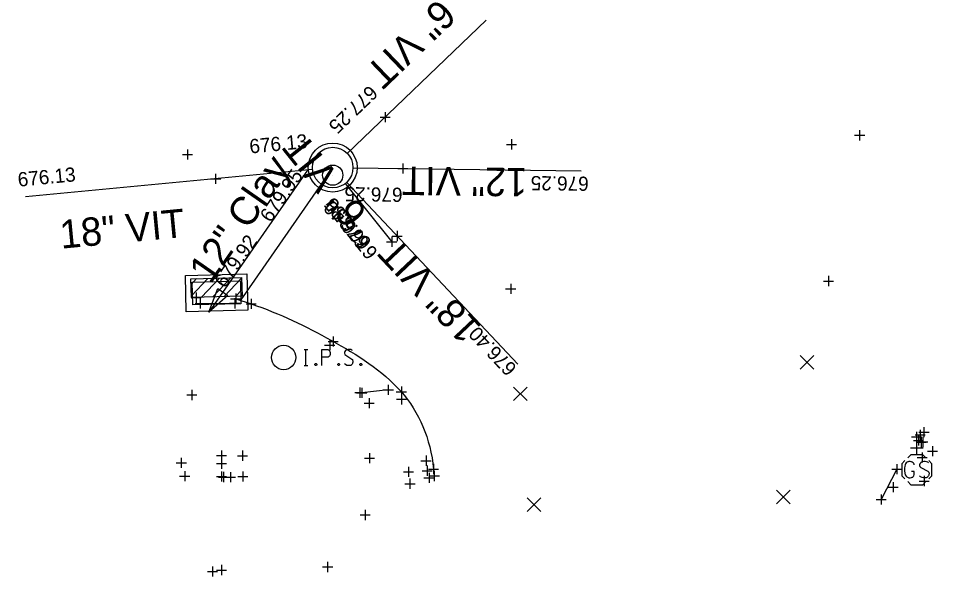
# Model space of a CAD drawing. Extents: x 2188719 to 2189819, y 654569 to 659504.
# Drawn here: x 2188973.7 to 2189064.4, y 655562.7 to 655617.7 of the extents above; entities that cross this region are included whole.
import ezdxf

# ---------------------------------------------------------------- set-up
doc = ezdxf.new("R2010")
doc.units = 0
for name, color, linetype in [('DR_X_Cells', 7, 'Continuous'), ('DR_X_Elev_Flow', 7, 'Continuous'), ('DR_X_Storm_Sewer', 7, 'Continuous'), ('DR_X_Text', 7, 'Continuous'), ('GK_Drainage_Nodes', 7, 'Continuous'), ('PV_X_Curb', 7, 'Continuous'), ('PV_X_Driveway', 7, 'Continuous'), ('SC_Scratch1', 7, 'Continuous'), ('SV_P_Mon_Cells_Set', 7, 'Continuous'), ('SV_X_Random_Point', 7, 'Continuous'), ('SV_X_Shot_Marker', 7, 'Continuous'), ('UT_X_Gas_Cells', 7, 'Continuous')]:
    doc.layers.add(name, color=color, linetype=linetype)

msp = doc.modelspace()

# ---------------------------------------------------------------- linework, layer by layer
at = {"layer": 'DR_X_Cells'}
for p, q in [((2188991.306, 655592.065), (2188990.765, 655591.495)), ((2188992.436, 655592.093), (2188990.793, 655590.363)), ((2188993.565, 655592.121), (2188991.783, 655590.243)), ((2188994.695, 655592.149), (2188992.912, 655590.271)), ((2188995.752, 655592.101), (2188994.042, 655590.299)), ((2188995.78, 655590.968), (2188995.171, 655590.327))]:
    msp.add_line(p, q, dxfattribs=at)
for points in [[(2188996.372, 655588.939), (2188990.29, 655588.788), (2188990.202, 655592.371), (2188996.283, 655592.522)], [(2188995.795, 655590.342), (2188990.797, 655590.219), (2188990.751, 655592.052), (2188995.75, 655592.175)], [(2188995.689, 655589.59), (2188990.94, 655589.472), (2188990.885, 655591.721), (2188995.633, 655591.839)]]:
    msp.add_lwpolyline(points, close=True, dxfattribs=at)
for centre, radius in [((2189004.743, 655603.014), 2.417), ((2189004.743, 655603.014), 2), ((2189004.743, 655602.264), 1)]:
    msp.add_circle(centre, radius, dxfattribs=at)
at = {"layer": 'DR_X_Elev_Flow'}
for p, q in [((2189009.926, 655608.488), (2189009.926, 655607.488)), ((2189009.426, 655607.988), (2189010.426, 655607.988)), ((2189009.926, 655607.988), (2189009.926, 655607.988)), ((2189011.169, 655602.926), (2189012.169, 655602.926)), ((2189011.669, 655603.426), (2189011.669, 655602.426)), ((2189011.669, 655602.926), (2189011.669, 655602.926)), ((2188993.193, 655602.411), (2188993.193, 655601.411)), ((2188992.693, 655601.911), (2188993.693, 655601.911)), ((2188993.193, 655601.911), (2188993.193, 655601.911)), ((2189011.112, 655596.763), (2189011.112, 655595.763)), ((2189010.067, 655595.704), (2189011.067, 655595.704)), ((2189010.567, 655596.204), (2189010.567, 655595.204)), ((2189010.567, 655595.704), (2189010.567, 655595.704)), ((2189010.612, 655596.263), (2189011.612, 655596.263)), ((2189011.112, 655596.263), (2189011.112, 655596.263))]:
    msp.add_line(p, q, dxfattribs=at)
at = {"layer": 'DR_X_Storm_Sewer'}
for p, q in [((2189006.186, 655604.399), (2189019.897, 655617.557)), ((2189006.743, 655602.989), (2189029.28, 655602.701)), ((2189002.752, 655602.824), (2188974.417, 655600.117)), ((2189003.602, 655601.371), (2188995.68, 655589.964)), ((2189005.989, 655601.45), (2189010.567, 655595.704)), ((2189006.115, 655601.559), (2189023.023, 655583.639))]:
    msp.add_line(p, q, dxfattribs=at)
at = {"layer": 'DR_X_Text'}
msp.add_line((2189002.259, 655602.768), (2188992.532, 655588.764), dxfattribs=at)
msp.add_lwpolyline([(2188992.532, 655588.764), (2188993.409, 655591.077), (2188994.394, 655590.393)], close=True, dxfattribs=at)
at = {"layer": 'GK_Drainage_Nodes'}
for p, q in [((2189004.743, 655605.014), (2189004.743, 655605.014)), ((2189004.743, 655603.014), (2189004.743, 655603.014)), ((2189004.743, 655603.014), (2189004.743, 655603.014)), ((2189004.743, 655602.264), (2189004.743, 655602.264)), ((2189004.743, 655601.014), (2189004.743, 655601.014)), ((2188993.242, 655592.447), (2188993.242, 655592.447)), ((2188993.259, 655591.78), (2188993.259, 655591.78)), ((2188990.912, 655590.597), (2188990.912, 655590.597)), ((2188993.287, 655590.655), (2188993.287, 655590.655)), ((2188993.296, 655590.281), (2188993.296, 655590.281)), ((2188993.296, 655590.281), (2188993.296, 655590.281)), ((2188995.661, 655590.714), (2188995.661, 655590.714)), ((2188993.315, 655589.531), (2188993.315, 655589.531)), ((2188993.331, 655588.864), (2188993.331, 655588.864))]:
    msp.add_line(p, q, dxfattribs=at)
msp.add_circle((2189004.743, 655603.014), 2, dxfattribs=at)
at = {"layer": 'PV_X_Curb'}
for p, q in [((2188991.654, 655589.62), (2188995.074, 655589.632)), ((2189010.231, 655581.098), (2189007.606, 655580.802))]:
    msp.add_line(p, q, dxfattribs=at)
at = {"layer": 'PV_X_Driveway'}
for p, q in [((2188995.173, 655590.088), (2188996.696, 655589.577)), ((2189014.701, 655573.293), (2189014.772, 655572.61)), ((2189060.412, 655573.28), (2189058.882, 655570.288))]:
    msp.add_line(p, q, dxfattribs=at)
msp.add_open_spline([(2188996.696, 655589.577), (2188999.557, 655588.617), (2189004.614, 655586.114), (2189012.179, 655581.475), (2189014.388, 655576.306), (2189014.701, 655573.293)], degree=3, dxfattribs=at)
at = {"layer": 'SV_P_Mon_Cells_Set'}
for points in [[(2189001.926, 655585.09), (2189002.279, 655585.09)], [(2189002.102, 655583.49), (2189002.102, 655585.09)], [(2189003.668, 655583.49), (2189003.668, 655585.09), (2189004.197, 655585.09), (2189004.252, 655585.077), (2189004.329, 655585.052), (2189004.362, 655585.027), (2189004.395, 655585.001), (2189004.439, 655584.938), (2189004.472, 655584.875), (2189004.494, 655584.775), (2189004.494, 655584.623), (2189004.483, 655584.573), (2189004.461, 655584.497), (2189004.417, 655584.409), (2189004.373, 655584.372), (2189004.34, 655584.346), (2189004.285, 655584.321), (2189004.197, 655584.309), (2189003.668, 655584.309)], [(2189006.677, 655584.976), (2189006.655, 655585.001), (2189006.622, 655585.027), (2189006.523, 655585.064), (2189006.401, 655585.09), (2189006.313, 655585.09), (2189006.28, 655585.09), (2189006.137, 655585.052), (2189006.016, 655584.976), (2189005.938, 655584.875), (2189005.916, 655584.775), (2189005.916, 655584.699), (2189005.938, 655584.598), (2189006.027, 655584.51), (2189006.633, 655584.132), (2189006.688, 655584.082), (2189006.71, 655584.031), (2189006.732, 655583.956), (2189006.732, 655583.88), (2189006.721, 655583.805), (2189006.71, 655583.754), (2189006.688, 655583.691), (2189006.666, 655583.641), (2189006.644, 655583.603), (2189006.611, 655583.565), (2189006.578, 655583.54), (2189006.534, 655583.515), (2189006.501, 655583.502), (2189006.401, 655583.49), (2189006.247, 655583.49), (2189006.148, 655583.515), (2189006.004, 655583.603), (2189005.916, 655583.679)], [(2189001.926, 655583.49), (2189002.279, 655583.49)], [(2189003.061, 655583.704), (2189003.116, 655583.704), (2189003.15, 655583.679), (2189003.183, 655583.628), (2189003.183, 655583.565), (2189003.15, 655583.515), (2189003.116, 655583.49), (2189003.061, 655583.49), (2189003.028, 655583.515), (2189002.995, 655583.565), (2189002.995, 655583.628), (2189003.028, 655583.679), (2189003.061, 655583.704)], [(2189005.31, 655583.704), (2189005.365, 655583.704), (2189005.398, 655583.679), (2189005.431, 655583.628), (2189005.431, 655583.565), (2189005.398, 655583.515), (2189005.365, 655583.49), (2189005.31, 655583.49), (2189005.277, 655583.515), (2189005.244, 655583.565), (2189005.244, 655583.628), (2189005.277, 655583.679), (2189005.31, 655583.704)], [(2189007.493, 655583.704), (2189007.548, 655583.704), (2189007.581, 655583.679), (2189007.614, 655583.628), (2189007.614, 655583.565), (2189007.581, 655583.515), (2189007.548, 655583.49), (2189007.493, 655583.49), (2189007.459, 655583.515), (2189007.427, 655583.565), (2189007.427, 655583.628), (2189007.459, 655583.679), (2189007.493, 655583.704)]]:
    msp.add_lwpolyline(points, dxfattribs=at)
msp.add_circle((2188999.907, 655584.288), 1.2, dxfattribs=at)
at = {"layer": 'SV_X_Random_Point'}
for p, q in [((2189050.889, 655583.147), (2189052.223, 655584.482)), ((2189050.889, 655584.482), (2189052.223, 655583.147)), ((2189022.601, 655580.034), (2189023.935, 655581.369)), ((2189022.601, 655581.369), (2189023.935, 655580.034)), ((2189048.542, 655569.865), (2189049.876, 655571.2)), ((2189048.542, 655571.2), (2189049.876, 655569.865)), ((2189023.942, 655569.118), (2189025.276, 655570.453)), ((2189023.942, 655570.453), (2189025.276, 655569.118))]:
    msp.add_line(p, q, dxfattribs=at)
at = {"layer": 'SV_X_Shot_Marker'}
for p, q in [((2189056.747, 655606.694), (2189056.747, 655605.694)), ((2189022.394, 655605.803), (2189022.394, 655604.803)), ((2189056.247, 655606.194), (2189057.247, 655606.194)), ((2189056.747, 655606.194), (2189056.747, 655606.194)), ((2188990.408, 655604.806), (2188990.408, 655603.806)), ((2189021.894, 655605.303), (2189022.894, 655605.303)), ((2189022.394, 655605.303), (2189022.394, 655605.303)), ((2188989.908, 655604.306), (2188990.908, 655604.306)), ((2188990.408, 655604.306), (2188990.408, 655604.306)), ((2189053.678, 655592.326), (2189053.678, 655591.326)), ((2189021.809, 655591.049), (2189022.809, 655591.049)), ((2189022.309, 655591.549), (2189022.309, 655590.549)), ((2189022.309, 655591.049), (2189022.309, 655591.049)), ((2189053.178, 655591.826), (2189054.178, 655591.826)), ((2189053.678, 655591.826), (2189053.678, 655591.826)), ((2188990.777, 655590.188), (2188991.777, 655590.188)), ((2188991.277, 655590.688), (2188991.277, 655589.688)), ((2188991.277, 655590.188), (2188991.277, 655590.188)), ((2188995.173, 655590.588), (2188995.173, 655589.588)), ((2188991.154, 655589.62), (2188992.154, 655589.62)), ((2188991.654, 655590.12), (2188991.654, 655589.12)), ((2188991.654, 655589.62), (2188991.654, 655589.62)), ((2188994.574, 655589.632), (2188995.574, 655589.632)), ((2188994.673, 655590.088), (2188995.673, 655590.088)), ((2188995.074, 655590.132), (2188995.074, 655589.132)), ((2188995.074, 655589.632), (2188995.074, 655589.632)), ((2188995.173, 655590.088), (2188995.173, 655590.088)), ((2188996.196, 655589.577), (2188997.196, 655589.577)), ((2188996.696, 655590.077), (2188996.696, 655589.077)), ((2188996.696, 655589.577), (2188996.696, 655589.577)), ((2189004.294, 655585.863), (2189005.294, 655585.863)), ((2189004.447, 655585.998), (2189004.447, 655584.998)), ((2189004.794, 655586.363), (2189004.794, 655585.363)), ((2189004.794, 655585.863), (2189004.794, 655585.863)), ((2189003.947, 655585.498), (2189004.947, 655585.498)), ((2189004.447, 655585.498), (2189004.447, 655585.498)), ((2188990.844, 655581.096), (2188990.844, 655580.096)), ((2189007.412, 655581.327), (2189007.412, 655580.327)), ((2189007.606, 655581.302), (2189007.606, 655580.302)), ((2189009.731, 655581.098), (2189010.731, 655581.098)), ((2189010.231, 655581.598), (2189010.231, 655580.598)), ((2189010.231, 655581.098), (2189010.231, 655581.098)), ((2189011.519, 655581.416), (2189011.519, 655580.416)), ((2188990.344, 655580.596), (2188991.344, 655580.596)), ((2188990.844, 655580.596), (2188990.844, 655580.596)), ((2189006.912, 655580.827), (2189007.912, 655580.827)), ((2189007.106, 655580.802), (2189008.106, 655580.802)), ((2189007.412, 655580.827), (2189007.412, 655580.827)), ((2189007.606, 655580.802), (2189007.606, 655580.802)), ((2189008.335, 655580.278), (2189008.335, 655579.278)), ((2189011.019, 655580.916), (2189012.019, 655580.916)), ((2189011.037, 655580.169), (2189012.037, 655580.169)), ((2189011.519, 655580.916), (2189011.519, 655580.916)), ((2189011.537, 655580.669), (2189011.537, 655579.669)), ((2189011.537, 655580.169), (2189011.537, 655580.169)), ((2189007.835, 655579.778), (2189008.835, 655579.778)), ((2189008.335, 655579.778), (2189008.335, 655579.778)), ((2189062.228, 655576.657), (2189063.228, 655576.657)), ((2189062.368, 655576.958), (2189062.368, 655575.958)), ((2189062.552, 655576.598), (2189062.552, 655575.598)), ((2189062.598, 655576.931), (2189063.598, 655576.931)), ((2189062.728, 655577.157), (2189062.728, 655576.157)), ((2189062.728, 655576.657), (2189062.728, 655576.657)), ((2189063.098, 655577.431), (2189063.098, 655576.431)), ((2189063.098, 655576.931), (2189063.098, 655576.931)), ((2189061.868, 655576.458), (2189062.868, 655576.458)), ((2189062.052, 655576.098), (2189063.052, 655576.098)), ((2189062.321, 655575.953), (2189063.321, 655575.953)), ((2189062.368, 655576.458), (2189062.368, 655576.458)), ((2189062.481, 655575.963), (2189063.481, 655575.963)), ((2189062.552, 655576.098), (2189062.552, 655576.098)), ((2189062.821, 655576.453), (2189062.821, 655575.453)), ((2189062.821, 655575.953), (2189062.821, 655575.953)), ((2189062.981, 655576.463), (2189062.981, 655575.463)), ((2189062.981, 655575.963), (2189062.981, 655575.963)), ((2188993.771, 655575.11), (2188993.771, 655574.11)), ((2188995.833, 655575.105), (2188995.833, 655574.105)), ((2189008.383, 655574.872), (2189008.383, 655573.872)), ((2189062.91, 655574.925), (2189062.91, 655573.925)), ((2189063.444, 655575.047), (2189064.444, 655575.047)), ((2189063.944, 655575.547), (2189063.944, 655574.547)), ((2189063.944, 655575.047), (2189063.944, 655575.047)), ((2188989.3, 655573.9), (2188990.3, 655573.9)), ((2188989.8, 655574.4), (2188989.8, 655573.4)), ((2188989.8, 655573.9), (2188989.8, 655573.9)), ((2188993.271, 655574.61), (2188994.271, 655574.61)), ((2188993.276, 655573.825), (2188994.276, 655573.825)), ((2188993.771, 655574.61), (2188993.771, 655574.61)), ((2188993.776, 655574.325), (2188993.776, 655573.325)), ((2188993.776, 655573.825), (2188993.776, 655573.825)), ((2188995.333, 655574.605), (2188996.333, 655574.605)), ((2188995.833, 655574.605), (2188995.833, 655574.605)), ((2189007.883, 655574.372), (2189008.883, 655574.372)), ((2189008.383, 655574.372), (2189008.383, 655574.372)), ((2189013.452, 655574.111), (2189014.452, 655574.111)), ((2189013.952, 655574.611), (2189013.952, 655573.611)), ((2189013.952, 655574.111), (2189013.952, 655574.111)), ((2189062.41, 655574.425), (2189063.41, 655574.425)), ((2189062.91, 655574.425), (2189062.91, 655574.425)), ((2188990.136, 655573.093), (2188990.136, 655572.093)), ((2188993.76, 655573.061), (2188993.76, 655572.061)), ((2188993.978, 655573.002), (2188993.978, 655572.002)), ((2188994.65, 655572.999), (2188994.65, 655571.999)), ((2188995.868, 655573.052), (2188995.868, 655572.052)), ((2189011.718, 655573.018), (2189012.718, 655573.018)), ((2189012.218, 655573.518), (2189012.218, 655572.518)), ((2189012.218, 655573.018), (2189012.218, 655573.018)), ((2189013.557, 655573.12), (2189014.557, 655573.12)), ((2189013.575, 655573.125), (2189014.575, 655573.125)), ((2189014.057, 655573.62), (2189014.057, 655572.62)), ((2189014.057, 655573.12), (2189014.057, 655573.12)), ((2189014.075, 655573.625), (2189014.075, 655572.625)), ((2189014.075, 655573.125), (2189014.075, 655573.125)), ((2189014.201, 655573.293), (2189015.201, 655573.293)), ((2189014.253, 655572.924), (2189014.253, 655571.924)), ((2189014.701, 655573.793), (2189014.701, 655572.793)), ((2189014.701, 655573.293), (2189014.701, 655573.293)), ((2189014.772, 655573.11), (2189014.772, 655572.11)), ((2189059.912, 655573.28), (2189060.912, 655573.28)), ((2189060.412, 655573.78), (2189060.412, 655572.78)), ((2189060.412, 655573.28), (2189060.412, 655573.28)), ((2188989.636, 655572.593), (2188990.636, 655572.593)), ((2188990.136, 655572.593), (2188990.136, 655572.593)), ((2188993.26, 655572.561), (2188994.26, 655572.561)), ((2188993.478, 655572.502), (2188994.478, 655572.502)), ((2188993.76, 655572.561), (2188993.76, 655572.561)), ((2188993.978, 655572.502), (2188993.978, 655572.502)), ((2188994.15, 655572.499), (2188995.15, 655572.499)), ((2188994.65, 655572.499), (2188994.65, 655572.499)), ((2188995.368, 655572.552), (2188996.368, 655572.552)), ((2188995.868, 655572.552), (2188995.868, 655572.552)), ((2189012.368, 655572.346), (2189012.368, 655571.346)), ((2189013.753, 655572.424), (2189014.753, 655572.424)), ((2189014.253, 655572.424), (2189014.253, 655572.424)), ((2189014.272, 655572.61), (2189015.272, 655572.61)), ((2189014.772, 655572.61), (2189014.772, 655572.61)), ((2189060.046, 655571.997), (2189060.046, 655570.997)), ((2189062.615, 655572.11), (2189063.615, 655572.11)), ((2189063.115, 655572.61), (2189063.115, 655571.61)), ((2189063.115, 655572.11), (2189063.115, 655572.11)), ((2189011.868, 655571.846), (2189012.868, 655571.846)), ((2189012.368, 655571.846), (2189012.368, 655571.846)), ((2189059.546, 655571.497), (2189060.546, 655571.497)), ((2189060.046, 655571.497), (2189060.046, 655571.497)), ((2189058.382, 655570.288), (2189059.382, 655570.288)), ((2189058.882, 655570.788), (2189058.882, 655569.788)), ((2189058.882, 655570.288), (2189058.882, 655570.288)), ((2189007.44, 655568.762), (2189008.44, 655568.762)), ((2189007.94, 655569.262), (2189007.94, 655568.262)), ((2189007.94, 655568.762), (2189007.94, 655568.762)), ((2188993.773, 655563.832), (2188993.773, 655562.832)), ((2189004.242, 655564.136), (2189004.242, 655563.136)), ((2188992.372, 655563.187), (2188993.372, 655563.187)), ((2188992.872, 655563.687), (2188992.872, 655562.687)), ((2188992.872, 655563.187), (2188992.872, 655563.187)), ((2188993.273, 655563.332), (2188994.273, 655563.332)), ((2188993.773, 655563.332), (2188993.773, 655563.332)), ((2189003.742, 655563.636), (2189004.742, 655563.636)), ((2189004.242, 655563.636), (2189004.242, 655563.636))]:
    msp.add_line(p, q, dxfattribs=at)
at = {"layer": 'UT_X_Gas_Cells'}
for p, q in [((2189062.392, 655574.707), (2189062.392, 655575.977)), ((2189063.027, 655575.342), (2189061.754, 655575.342)), ((2189062.392, 655573.226), (2189062.392, 655573.226))]:
    msp.add_line(p, q, dxfattribs=at)
for points in [[(2189061.215, 655574.122), (2189060.91, 655573.819), (2189060.91, 655572.634), (2189061.212, 655572.332)], [(2189062.134, 655573.711), (2189062.121, 655573.773), (2189062.083, 655573.837), (2189062.02, 655573.899), (2189061.932, 655573.975), (2189061.869, 655574), (2189061.819, 655574.013), (2189061.743, 655574.026), (2189061.592, 655574.026), (2189061.529, 655574.013), (2189061.491, 655574), (2189061.441, 655573.975), (2189061.34, 655573.899), (2189061.277, 655573.811), (2189061.239, 655573.711), (2189061.214, 655573.572), (2189061.189, 655573.37), (2189061.189, 655573.106), (2189061.201, 655572.892), (2189061.252, 655572.728), (2189061.327, 655572.577), (2189061.391, 655572.526), (2189061.466, 655572.476), (2189061.605, 655572.426), (2189061.743, 655572.426), (2189061.882, 655572.451), (2189061.932, 655572.476), (2189061.983, 655572.501), (2189062.033, 655572.552), (2189062.083, 655572.627), (2189062.134, 655572.74), (2189062.134, 655573.055), (2189061.869, 655573.055)], [(2189063.289, 655574.402), (2189062.984, 655574.707), (2189061.799, 655574.707), (2189061.495, 655574.406)], [(2189063.532, 655573.912), (2189063.507, 655573.937), (2189063.469, 655573.963), (2189063.356, 655574), (2189063.217, 655574.026), (2189063.116, 655574.026), (2189063.078, 655574.026), (2189062.915, 655573.988), (2189062.776, 655573.912), (2189062.688, 655573.811), (2189062.663, 655573.711), (2189062.663, 655573.635), (2189062.688, 655573.534), (2189062.789, 655573.446), (2189063.482, 655573.068), (2189063.545, 655573.018), (2189063.57, 655572.967), (2189063.595, 655572.892), (2189063.595, 655572.816), (2189063.582, 655572.74), (2189063.57, 655572.69), (2189063.545, 655572.627), (2189063.519, 655572.577), (2189063.494, 655572.539), (2189063.456, 655572.501), (2189063.419, 655572.476), (2189063.368, 655572.451), (2189063.33, 655572.438), (2189063.217, 655572.426), (2189063.041, 655572.426), (2189062.927, 655572.451), (2189062.764, 655572.539), (2189062.663, 655572.614)], [(2189063.569, 655572.332), (2189063.872, 655572.634), (2189063.872, 655573.819), (2189063.569, 655574.122)], [(2189061.492, 655572.052), (2189061.799, 655571.746), (2189062.984, 655571.746), (2189063.289, 655572.049)]]:
    msp.add_lwpolyline(points, dxfattribs=at)

# ---------------------------------------------------------------- texts
at = {"layer": 'DR_X_Text'}
for s, rotation, p in [('6" VIT', 223.82119, (2189015.198, 655619.785)), ('6" VIT', 128.54607, (2189008.278, 655598.577)), ('12" Clay', 55.21838, (2188992.685, 655591.437)), ('12" VIT', 179.26957, (2189023.957, 655602.957)), ('18" VIT', 5.45705, (2188977.946, 655595.009)), ('18" VIT', 133.33353, (2189019.586, 655587.323))]:
    msp.add_text(s, height=2.8, rotation=rotation, dxfattribs=at).set_placement(p)
at = {"layer": 'SC_Scratch1'}
for s, rotation, p in [('677.25', 223.82119, (2189008.357, 655611.215)), ('676.13', 5.45705, (2188996.593, 655604.395)), ('676.13', 5.45705, (2188973.727, 655601.123)), ('679.95', 55.21838, (2188998.612, 655597.517)), ('676.25', 179.26957, (2189030.023, 655602.112)), ('676.25', 179.26957, (2189011.645, 655601.026)), ('676.35', 128.54607, (2189008.445, 655595.72)), ('676.40', 133.33353, (2189008.668, 655595.721)), ('676.35', 128.54607, (2189009.277, 655594.676)), ('679.92', 55.21838, (2188994.119, 655591.048)), ('676.40', 133.33353, (2189022.994, 655583.299))]:
    msp.add_text(s, height=1.4, rotation=rotation, dxfattribs=at).set_placement(p)

doc.saveas('drawing.dxf')
